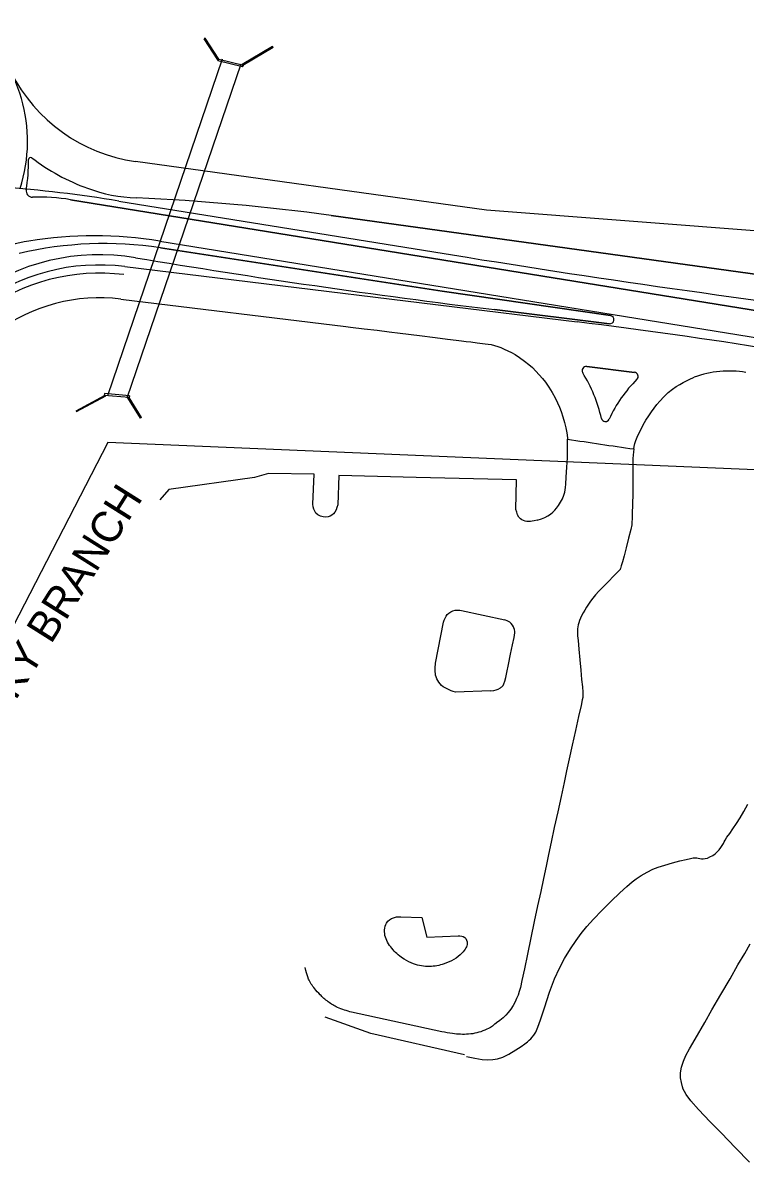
# Model space of a CAD drawing. Extents: x 1756435 to 1766932, y 416863 to 426859.
# Drawn here: x 1763112 to 1763464, y 423334 to 423897 of the extents above; entities that cross this region are included whole.
import ezdxf

# ---------------------------------------------------------------- set-up
doc = ezdxf.new("R2010")
doc.units = 0
for name, color, linetype in [('Exist Boundary City Limits', 7, 'Continuous'), ('Exist Hydro Stream or Body of Water Text', 7, 'Continuous'), ('Exist Roads EOP', 7, 'Continuous'), ('Exist Roads EOP Other', 7, 'Continuous'), ('Exist Structure Major Bridge WW', 7, 'Continuous'), ('Exist Structure Major Deck Tunnel Box Culvert', 7, 'Continuous'), ('Prop Horizontal Alignment', 7, 'Continuous'), ('Prop Lane Lines', 7, 'Continuous'), ('Prop Shade Light', 7, 'Continuous'), ('Prop Shade Medium', 7, 'Continuous')]:
    doc.layers.add(name, color=color, linetype=linetype)

msp = doc.modelspace()

# ---------------------------------------------------------------- linework, layer by layer
at = {"layer": 'Exist Boundary City Limits'}
msp.add_lwpolyline([(1762880.67, 423159.66), (1763610.22, 423060.06), (1763692.83, 423684.46), (1763583.09, 423697.89), (1763580.16, 423674.65), (1763153.55, 423692.65), (1763091.03, 423571.76), (1763039.83, 423506.29), (1762974.04, 423447.46), (1762934.14, 423389.22), (1762925.42, 423350.93), (1762898.59, 423287.45), (1762877.48, 423297.28), (1762869.53, 423205.69), (1762867.5, 423196.1), (1762876.5, 423188.61), (1762880.67, 423159.66)], dxfattribs=at)
at = {"layer": 'Exist Roads EOP'}
for points in [[(1763362.51, 423654.79), (1763364.72, 423655.46), (1763366.34, 423656.14), (1763367.78, 423656.91), (1763369.05, 423657.77), (1763370.15, 423658.72), (1763371.15, 423659.7), (1763372.08, 423660.73), (1763373.03, 423662.03), (1763374, 423663.6), (1763374.86, 423665.29), (1763375.57, 423667.03), (1763376.03, 423668.45), (1763376.26, 423669.56), (1763376.42, 423670.81), (1763376.54, 423672.46), (1763376.76, 423675.76), (1763377.07, 423680.61), (1763377.29, 423685.25), (1763377.41, 423689.33), (1763377.4, 423692.55), (1763377.32, 423694.3)], [(1763409.65, 423689.54), (1763409.44, 423688.01), (1763409.32, 423686.66), (1763409.25, 423684.69), (1763409.19, 423681.52), (1763409.17, 423677.47), (1763409.19, 423672.87), (1763409.17, 423667.86), (1763409.04, 423662.57), (1763408.9, 423658.09), (1763408.83, 423655.49), (1763408.77, 423653.93), (1763408.63, 423652.57), (1763408.17, 423650.32), (1763407.12, 423646.1), (1763405.88, 423641.35), (1763404.88, 423637.52), (1763404.1, 423634.6), (1763403.55, 423632.57), (1763403.18, 423631.34), (1763403.05, 423630.99), (1763402.95, 423630.81), (1763402.67, 423630.51), (1763402.19, 423629.98), (1763401.26, 423629.01), (1763399.62, 423627.39), (1763397.48, 423625.25), (1763394.99, 423622.74), (1763392.65, 423620.31), (1763390.97, 423618.44), (1763389.7, 423616.88), (1763388.59, 423615.42), (1763387.59, 423614), (1763386.64, 423612.56), (1763385.75, 423611.12), (1763384.95, 423609.69), (1763384.26, 423608.33), (1763383.71, 423607.12), (1763383.27, 423605.99), (1763382.89, 423604.92), (1763382.59, 423603.9), (1763382.39, 423602.94), (1763382.25, 423602), (1763382.19, 423601), (1763382.2, 423599.89), (1763382.3, 423598.59), (1763382.52, 423596.27), (1763382.9, 423592.06), (1763383.35, 423586.94), (1763383.81, 423581.9), (1763384.24, 423577.35), (1763384.6, 423573.72), (1763384.84, 423571.1), (1763384.9, 423569.61), (1763384.8, 423568.58), (1763384.57, 423567.37), (1763383.97, 423564.69), (1763382.76, 423559.28), (1763381.22, 423552.39), (1763379.66, 423545.3), (1763378.19, 423538.6), (1763376.95, 423532.9), (1763375.7, 423527.15), (1763374.22, 423520.32), (1763372.59, 423512.87), (1763370.92, 423505.25), (1763369.36, 423498.09), (1763368.09, 423492.04), (1763366.92, 423486.4), (1763365.67, 423480.49), (1763364.32, 423474.11), (1763362.81, 423467.08), (1763361.2, 423459.5), (1763359.52, 423451.47), (1763357.87, 423443.57), (1763356.35, 423436.36), (1763355.13, 423430.68), (1763354.39, 423427.37), (1763353.86, 423425.36), (1763353.26, 423423.59), (1763352.59, 423421.94), (1763351.83, 423420.3), (1763350.9, 423418.62), (1763349.72, 423416.85), (1763348.46, 423415.2), (1763347.28, 423413.86), (1763346, 423412.64), (1763344.46, 423411.35), (1763342.82, 423410.09), (1763341.83, 423409.4)], [(1763339.81, 423571.79), (1763341.48, 423571.97), (1763342.55, 423572.22), (1763343.61, 423572.64), (1763344.66, 423573.22), (1763345.09, 423573.51), (1763345.44, 423573.8), (1763345.71, 423574.09), (1763345.95, 423574.41), (1763346.41, 423575.26), (1763346.85, 423576.45), (1763347.31, 423578.23), (1763347.82, 423580.75), (1763348.62, 423584.63), (1763349.67, 423589.66), (1763350.6, 423594.14), (1763351.33, 423597.71), (1763351.64, 423600.02), (1763351.64, 423600.68), (1763351.47, 423601.63), (1763351.23, 423602.47), (1763351.06, 423602.87), (1763350.55, 423603.73), (1763349.87, 423604.6), (1763349.37, 423605.12), (1763349.22, 423605.23), (1763348.87, 423605.39), (1763348.3, 423605.64), (1763346.79, 423606.28)], [(1763328.16, 423393.69), (1763332.28, 423392.88), (1763335.8, 423392.32), (1763338.5, 423392.14), (1763340.95, 423392.24), (1763343.34, 423392.66), (1763345.79, 423393.46), (1763348.79, 423394.92), (1763352.22, 423396.95), (1763354.87, 423398.63), (1763356.58, 423399.85), (1763357.82, 423400.84), (1763358.69, 423401.64), (1763359.43, 423402.37), (1763360.11, 423403.09), (1763360.91, 423404.11), (1763361.86, 423405.59), (1763362.92, 423408.03), (1763364.17, 423411.68), (1763366.09, 423417.45), (1763368.66, 423425.03), (1763371.11, 423431.53), (1763373.39, 423436.68), (1763375.98, 423441.53), (1763378.86, 423446.2), (1763381.56, 423450.22), (1763384.06, 423453.62), (1763386.85, 423457.02), (1763390.06, 423460.59), (1763394.06, 423464.76), (1763398.7, 423469.4), (1763402.83, 423473.39), (1763406.24, 423476.53), (1763408.81, 423478.78), (1763410.73, 423480.3), (1763413.16, 423481.86), (1763416.17, 423483.53), (1763418.96, 423484.89), (1763421.54, 423485.93), (1763424.72, 423486.98), (1763428.48, 423488.08), (1763432.04, 423489.01), (1763435.15, 423489.73), (1763437.31, 423490.19), (1763438.54, 423490.4), (1763439.48, 423490.46), (1763440.28, 423490.42), (1763441.06, 423490.3), (1763441.86, 423490.13), (1763442.65, 423490.02), (1763443.44, 423489.99), (1763444.38, 423490.1), (1763445.49, 423490.39), (1763446.75, 423490.91), (1763448.11, 423491.66), (1763449.32, 423492.5), (1763450.33, 423493.41), (1763451.25, 423494.42), (1763452.09, 423495.49), (1763452.75, 423496.49), (1763453.26, 423497.41), (1763453.7, 423498.27), (1763454.15, 423499.15), (1763455.03, 423500.48), (1763456.36, 423502.32), (1763457.92, 423504.54), (1763459.64, 423507.13), (1763461.41, 423509.99), (1763463.21, 423513.11), (1763465.23, 423516.58)], [(1763465.98, 423342.28), (1763459.18, 423349.28), (1763452.13, 423356.55), (1763446.89, 423361.96), (1763441.14, 423368), (1763437.49, 423372.16), (1763435.14, 423375.31), (1763434.32, 423376.65), (1763433.71, 423377.88), (1763433.33, 423378.97), (1763432.83, 423381.09), (1763432.47, 423383.3), (1763432.39, 423384.47), (1763432.44, 423385.74), (1763432.93, 423388.56), (1763433.84, 423391.46), (1763435.06, 423394.17), (1763436.85, 423397.48), (1763439.5, 423402.18), (1763444.19, 423410.32), (1763447.73, 423416.45), (1763452.08, 423423.96), (1763456.53, 423431.64), (1763460.39, 423438.31), (1763463.65, 423443.97), (1763466.31, 423448.61)]]:
    msp.add_lwpolyline(points, dxfattribs=at)
at = {"layer": 'Exist Roads EOP Other'}
for p, q in [((1763362.51, 423654.79), (1763361.1, 423654.55)), ((1763325.79, 423610.93), (1763346.79, 423606.28)), ((1763313.06, 423585.32), (1763316.99, 423605.29)), ((1763339.81, 423571.79), (1763322.8, 423571.08)), ((1763294.59, 423461.76), (1763296.25, 423461.69)), ((1763296.25, 423461.69), (1763306.48, 423461.5)), ((1763306.48, 423461.5), (1763308.85, 423451.85)), ((1763308.85, 423451.85), (1763324.08, 423452.58)), ((1763249.96, 423435.58), (1763249.63, 423437.13)), ((1763316.08, 423405.8), (1763272.21, 423415.32)), ((1763341.64, 423409.28), (1763340.82, 423408.44))]:
    msp.add_line(p, q, dxfattribs=at)
for points in [[(1763253.33, 423662.63), (1763253.97, 423677.28), (1763231.8, 423677.54), (1763224.91, 423675.66), (1763183.12, 423669.76), (1763178.77, 423664.83)], [(1763352.27, 423660), (1763352.5, 423674.57), (1763303.73, 423675.68), (1763265.95, 423676.58), (1763265.43, 423662.3)], [(1763327.27, 423394.63), (1763281.6, 423405.01), (1763259.39, 423412.93)]]:
    msp.add_lwpolyline(points, dxfattribs=at)
for points in [[(1763265.43, 423662.3), (1763263.36, 423657.9), (1763259.72, 423656.37), (1763254.86, 423658.29), (1763253.33, 423662.63)], [(1763361.1, 423654.55), (1763357.52, 423654.28), (1763354.47, 423655.48), (1763352.27, 423660)], [(1763316.99, 423605.29), (1763318.83, 423608.89), (1763322.59, 423611.06), (1763325.79, 423610.93)], [(1763322.8, 423571.08), (1763315.3, 423575.15), (1763313.34, 423578.63), (1763313.06, 423585.32)], [(1763324.08, 423452.58), (1763327.29, 423451.71), (1763328.51, 423448.82), (1763327.84, 423446.62), (1763326.04, 423444.17), (1763317.25, 423438.83), (1763310.23, 423437.54), (1763302.43, 423438.84), (1763297.82, 423441.11), (1763292.4, 423445.74), (1763288.69, 423451.85), (1763289.25, 423458.74), (1763292.57, 423461.34), (1763294.59, 423461.76)], [(1763272.21, 423415.32), (1763265.38, 423417.66), (1763260.77, 423420.38), (1763256.86, 423423.85), (1763254.23, 423426.74), (1763251.26, 423431.47), (1763249.96, 423435.58)], [(1763340.82, 423408.44), (1763337.06, 423406.55), (1763329.19, 423404.61), (1763321.36, 423404.91), (1763316.08, 423405.8)]]:
    msp.add_spline(points, degree=3, dxfattribs=at)
at = {"layer": 'Exist Structure Major Bridge WW'}
for points in [[(1763207.53, 423879.37), (1763200.85, 423889.6), (1763200.34, 423889.28)], [(1763207.53, 423879.37), (1763207.02, 423879.05), (1763200.34, 423889.28)], [(1763233.97, 423884.99), (1763233.64, 423885.51), (1763218.95, 423876.71)], [(1763233.97, 423884.99), (1763219.28, 423876.18), (1763218.95, 423876.71)], [(1763219.06, 423875.59), (1763207.09, 423878.51), (1763207.61, 423879.21)], [(1763219.06, 423875.59), (1763219.58, 423876.28), (1763207.61, 423879.21)], [(1763138.04, 423708.05), (1763152.25, 423715.75), (1763152.5, 423715.41)], [(1763138.04, 423708.05), (1763138.28, 423707.7), (1763152.5, 423715.41)], [(1763164.11, 423715.42), (1763151.9, 423716.5), (1763151.73, 423715.62)], [(1763164.11, 423715.42), (1763163.93, 423714.54), (1763151.73, 423715.62)], [(1763169.9, 423704.87), (1763163.81, 423714.64), (1763163.24, 423714.38)], [(1763169.9, 423704.87), (1763169.33, 423704.61), (1763163.24, 423714.38)]]:
    msp.add_lwpolyline(points, dxfattribs=at)
at = {"layer": 'Exist Structure Major Deck Tunnel Box Culvert'}
for p, q in [((1763209.16, 423879.34), (1763153.27, 423715.48)), ((1763162.94, 423714.42), (1763218.47, 423876.97))]:
    msp.add_line(p, q, dxfattribs=at)
at = {"layer": 'Prop Horizontal Alignment'}
msp.add_line((1763158.88, 423810.25), (1763321.33, 423783.98), dxfattribs=at)
for centre, radius, start, end in [((1763039.37, 423839.28), 75, 342.1749, 50.1445), ((1763047.17, 423119.22), 700, 80.81671, 90.30949), ((1764278.89, 429707.08), 6000, 260.81671, 263.023399), ((1763149.5, 423678.12), 97, 83.0234, 126.251)]:
    msp.add_arc(centre, radius, start, end, dxfattribs=at)
at = {"layer": 'Prop Lane Lines'}
for p, q in [((1763178.83, 423790.71), (1763552.88, 423730.24)), ((1763161.77, 423778.37), (1763382, 423751.42))]:
    msp.add_line(p, q, dxfattribs=at)
for centre, radius, start, end in [((1763146.91, 423593.27), 200, 80.8167, 99.1664), ((1763128.11, 423709.76), 82, 99.1664, 124.4163), ((1763149.5, 423678.12), 101, 83.0234, 126.251), ((1763078.34, 421269.93), 2500, 80.8167, 83.0234)]:
    msp.add_arc(centre, radius, start, end, dxfattribs=at)
at = {"layer": 'Prop Shade Light'}
for p, q in [((1763337.9, 423805.82), (1763166.96, 423829.5)), ((1763571.42, 423740.41), (1763135.37, 423810.9)), ((1763536.79, 423790.39), (1763337.9, 423805.82)), ((1763262.21, 423803.18), (1763609.64, 423755.05)), ((1763179.1, 423787.46), (1763316.39, 423766.44)), ((1763316.39, 423766.44), (1763398.28, 423754.47)), ((1763159.82, 423762.49), (1763269.34, 423749.09)), ((1763397.75, 423750.5), (1763341.74, 423757.36)), ((1763386.72, 423729.69), (1763409.99, 423726.84)), ((1763409.99, 423726.84), (1763386.72, 423729.69))]:
    msp.add_line(p, q, dxfattribs=at)
for points in [[(1763269.34, 423749.09), (1763271.75, 423748.81), (1763278.33, 423748.04), (1763284.64, 423747.3), (1763290.49, 423746.6), (1763295.87, 423745.94), (1763305.27, 423744.75), (1763312.95, 423743.78), (1763318.91, 423743.02), (1763323.09, 423742.49), (1763325.69, 423742.17), (1763327.95, 423741.9), (1763330.22, 423741.63), (1763333.4, 423741.25), (1763337.33, 423740.77), (1763340.2, 423740.33), (1763341.86, 423739.92), (1763343.38, 423739.44), (1763344.92, 423738.87), (1763346.59, 423738.17), (1763348.36, 423737.34), (1763350.1, 423736.45), (1763351.84, 423735.46), (1763353.98, 423734.06), (1763356.47, 423732.28), (1763358.58, 423730.63), (1763360.28, 423729.13), (1763361.94, 423727.48), (1763363.6, 423725.66), (1763365.16, 423723.84), (1763366.63, 423721.99), (1763368.2, 423719.69), (1763369.86, 423716.97), (1763371.28, 423714.4), (1763372.44, 423712.06), (1763373.4, 423709.86), (1763374.22, 423707.71), (1763375.05, 423705.22), (1763375.88, 423702.43), (1763376.54, 423699.78), (1763377, 423697.34), (1763377.28, 423694.98), (1763377.32, 423694.3)], [(1763409.66, 423689.54), (1763409.88, 423690.73), (1763410.2, 423692.12), (1763410.65, 423693.6), (1763411.32, 423695.28), (1763412.17, 423697.13), (1763413.16, 423699.13), (1763414.29, 423701.26), (1763415.58, 423703.48), (1763416.92, 423705.66), (1763418.22, 423707.66), (1763419.51, 423709.48), (1763420.85, 423711.14), (1763422.4, 423712.87), (1763424.34, 423714.94), (1763426.43, 423716.97), (1763428.44, 423718.59), (1763430.33, 423719.89), (1763432.08, 423720.98), (1763433.71, 423721.91), (1763435.26, 423722.75), (1763436.88, 423723.54), (1763438.69, 423724.3), (1763439.11, 423724.45)]]:
    msp.add_lwpolyline(points, dxfattribs=at)
for centre, radius, start, end in [((1763177.94, 423908.74), 80, 206.6249, 262.1129), ((1763034.88, 423829.11), 80, 350.318, 0.952), ((1763115.87, 423830.45), 1, 52.662, 180.952), ((1763178.34, 423912.34), 102, 232.662, 250.0572), ((1763116.7, 423815.15), 3, 170.318, 271.5113), ((1763170.83, 423891.66), 80, 250.0572, 267.5719), ((1763119.41, 423712.18), 100, 80.8167, 91.5113), ((1763125.12, 422813.63), 999, 82.11293, 87.57188), ((1763151.86, 423609.54), 180, 81.2942, 103.3291), ((1763149.5, 423678.12), 106, 80.4941, 126.251), ((1763827.6, 427727.74), 4000, 260.49414, 263.0234), ((1763149.5, 423678.12), 85, 83.0234, 126.251), ((1763397.99, 423752.49), 2, 263.0234, 81.6819), ((1763386.48, 423727.71), 2, 83.0234, 211.828), ((1763386.48, 423727.71), 2, 83.0234, 211.828), ((1763322.75, 423688.15), 73, 12.8943, 31.828), ((1763322.75, 423688.15), 73, 12.8943, 31.828), ((1763409.75, 423724.86), 2, 314.8789, 83.0234), ((1763409.75, 423724.86), 2, 314.8789, 83.0234), ((1763456.25, 423677.48), 50, 80.8167, 110.0476), ((1763457.73, 423676.67), 66, 134.8789, 155.4839), ((1763457.73, 423676.67), 66, 134.8789, 155.4839), ((1763395.86, 423704.89), 2, 192.8943, 282.2026), ((1763395.86, 423704.89), 2, 192.8943, 335.4839), ((1763395.86, 423704.89), 2, 282.2026, 335.4839), ((1764278.89, 429707.08), 6080, 261.472467, 261.780526)]:
    msp.add_arc(centre, radius, start, end, dxfattribs=at)
at = {"layer": 'Prop Shade Medium'}
for p, q in [((1763135.37, 423810.9), (1763571.42, 423740.41)), ((1763609.64, 423755.05), (1763262.21, 423803.18)), ((1763316.39, 423766.44), (1763179.1, 423787.46)), ((1763398.28, 423754.47), (1763316.39, 423766.44)), ((1763341.74, 423757.36), (1763397.75, 423750.5))]:
    msp.add_line(p, q, dxfattribs=at)
for centre, radius, start, end in [((1763034.88, 423829.11), 80, 350.318, 0.952), ((1763115.87, 423830.45), 1, 117.1658, 180.952), ((1763115.87, 423830.45), 1, 52.662, 117.1658), ((1763178.34, 423912.34), 102, 232.662, 250.0572), ((1763116.7, 423815.15), 3, 170.318, 271.5113), ((1763170.83, 423891.66), 80, 250.0572, 267.5719), ((1763119.41, 423712.18), 100, 80.8167, 91.5113), ((1763125.12, 422813.63), 999, 82.11293, 87.57188), ((1763151.86, 423609.54), 180, 81.2942, 103.3291), ((1763149.5, 423678.12), 106, 80.4941, 126.251), ((1763827.6, 427727.74), 4000, 260.49414, 263.0234), ((1763397.99, 423752.49), 2, 263.0234, 81.6819)]:
    msp.add_arc(centre, radius, start, end, dxfattribs=at)

# ---------------------------------------------------------------- texts
at = {"layer": 'Exist Hydro Stream or Body of Water Text'}
msp.add_text('ROCKY BRANCH', height=15, rotation=57.8016, dxfattribs=at).set_placement((1763084.8, 423529.06))

doc.saveas('drawing.dxf')
